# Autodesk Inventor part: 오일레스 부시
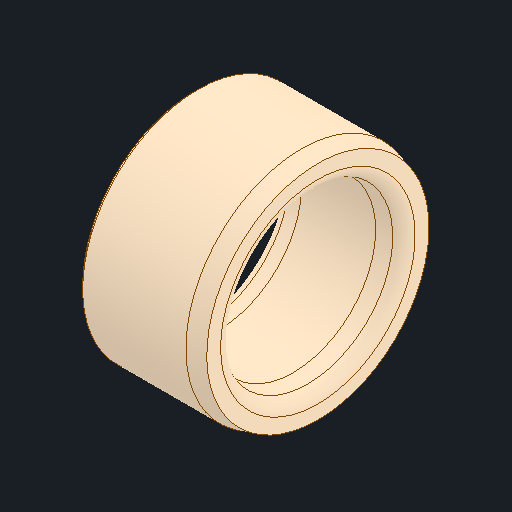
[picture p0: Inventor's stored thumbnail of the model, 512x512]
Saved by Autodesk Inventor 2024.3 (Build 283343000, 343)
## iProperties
Created: 2024-05
Part Number: 오일레스 부시
Material: 구리, 합금
Document SubType Name: Modeling
Designer: MyPc
Density: 8.92 g/cm^3
Appearance: 기본값
Author: jhkim
Sending System: Autodesk Inventor 2025
Preprocessor: ST-DEVELOPER v20
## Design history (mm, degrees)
node "오일레스 부시1"
node "솔리드2"
node "솔리드1"
